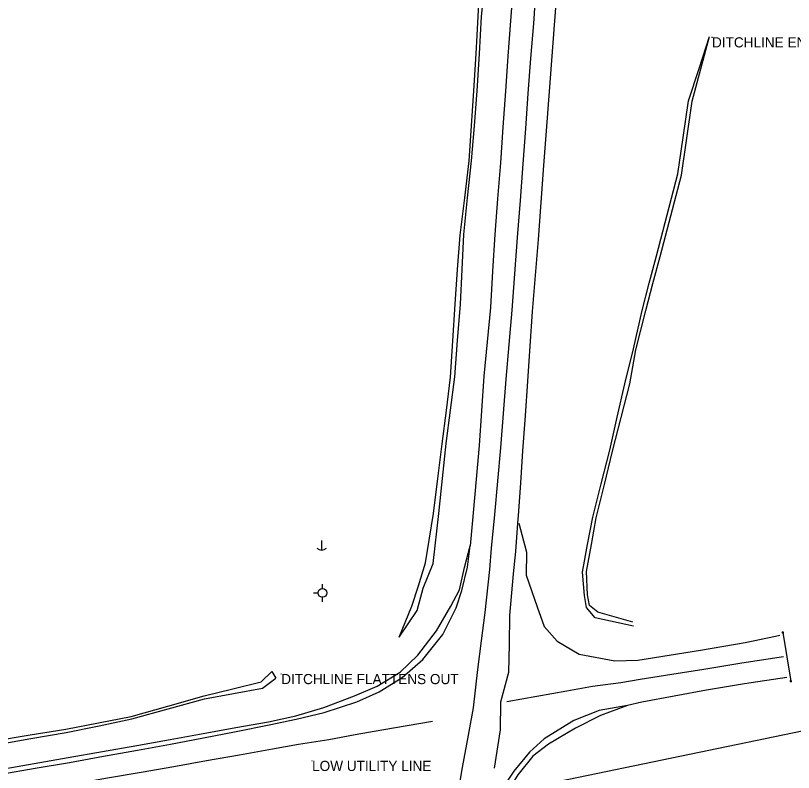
# Model space of a CAD drawing. Extents: x 1734049 to 1769984, y 344166 to 379510.
# Drawn here: x 1735978.3 to 1736361, y 378288.8 to 378661.3 of the extents above; entities that cross this region are included whole.
import ezdxf

# ---------------------------------------------------------------- set-up
doc = ezdxf.new("R2010")
doc.units = 0
for name, color, linetype in [('S_BASELINE', 7, 'Continuous'), ('S_BRIDGE', 7, 'Continuous'), ('S_DITCHLINE', 7, 'Continuous'), ('S_EDGE_PAVEMENT', 7, 'Continuous'), ('S_ELECTRIC_UTILITIES_ANNOT', 7, 'Continuous'), ('S_MSC_PT_SYM', 7, 'Continuous'), ('S_PAVEMENT_CROWN', 7, 'Continuous'), ('S_SHOULDER', 7, 'Continuous'), ('S_STR_PT_SYM', 7, 'Continuous'), ('S_SURVEY_TEXT_ANNOT', 7, 'Continuous'), ('S_UTILITY_POLE', 7, 'Continuous'), ('S_UTL_PT_SYM', 7, 'Continuous')]:
    doc.layers.add(name, color=color, linetype=linetype)

msp = doc.modelspace()

# ---------------------------------------------------------------- linework, layer by layer
at = {"layer": 'S_BASELINE'}
msp.add_line((1736142.34, 378263.18), (1737017.96, 378443.92), dxfattribs=at)
at = {"layer": 'S_BRIDGE'}
msp.add_line((1736355.87, 378357.66), (1736359.77, 378333.73), dxfattribs=at)
at = {"layer": 'S_DITCHLINE'}
for points in [[(1736166.97, 378355.41), (1736173.33, 378370.54), (1736176.51, 378380.59), (1736180, 378391.92), (1736183.91, 378416.22), (1736186.08, 378433.41), (1736188.26, 378450.6), (1736190.29, 378466.96), (1736192.32, 378483.33), (1736193.41, 378501.27), (1736194.51, 378519.21), (1736195.81, 378536.26), (1736197.11, 378553.32), (1736199.28, 378571.56), (1736201.45, 378589.8), (1736202.65, 378607.02), (1736203.84, 378624.23), (1736204.87, 378642.58), (1736205.89, 378660.93), (1736206.71, 378677.25)], [(1736166.97, 378355.41), (1736175.86, 378368.49), (1736178.79, 378379.51), (1736183.7, 378391.56), (1736186.47, 378416.28), (1736188.34, 378433.47), (1736190.21, 378450.66), (1736192.3, 378467.05), (1736194.4, 378483.44), (1736195.81, 378501.36), (1736197.22, 378519.27), (1736198.02, 378536.4), (1736198.82, 378553.54), (1736200.72, 378571.66), (1736202.61, 378589.78), (1736204.04, 378607.01), (1736205.48, 378624.24), (1736206.53, 378642.55), (1736207.58, 378660.87), (1736209.22, 378677.2)], [(1736282.39, 378360.8), (1736263.5, 378364.95), (1736259.24, 378369.92), (1736258.16, 378375.87), (1736257.22, 378387.43), (1736259.73, 378400.95), (1736262.25, 378414.47), (1736266.43, 378430.9), (1736270.61, 378447.33), (1736274.36, 378463.71), (1736278.1, 378480.1), (1736282.39, 378497.24), (1736286.63, 378516.13), (1736290.1, 378529.61), (1736293.58, 378543.08), (1736298.88, 378563.22), (1736304.18, 378583.35), (1736306.77, 378601.38), (1736309.36, 378619.41), (1736314.58, 378635.24), (1736319.79, 378651.08)], [(1736282.01, 378362.68), (1736264.78, 378367.72), (1736260.75, 378371.01), (1736259.7, 378376.15), (1736259.23, 378387.65), (1736261.63, 378400.9), (1736264.03, 378414.15), (1736268.05, 378430.5), (1736272.07, 378446.85), (1736276.29, 378463.46), (1736280.51, 378480.08), (1736283.43, 378496.82), (1736288.33, 378516.2), (1736291.9, 378529.43), (1736295.48, 378542.67), (1736300.71, 378562.74), (1736305.94, 378582.81), (1736308.56, 378601.01), (1736311.18, 378619.22), (1736315.49, 378635.15), (1736319.79, 378651.08)], [(1735967.77, 378304.3), (1735985.42, 378307.22), (1736003.06, 378310.15), (1736019.12, 378313.22), (1736035.18, 378316.28), (1736053.17, 378321.35), (1736071.17, 378326.42), (1736085.14, 378329.86), (1736099.11, 378333.29), (1736104.36, 378338.41), (1736106.32, 378335.19)], [(1735968.33, 378302.37), (1735985.79, 378305.41), (1736003.26, 378308.45), (1736019.39, 378311.78), (1736035.51, 378315.11), (1736053.35, 378320.04), (1736071.18, 378324.97), (1736085.52, 378327.65), (1736099.86, 378330.32), (1736106.32, 378335.19)]]:
    msp.add_lwpolyline(points, dxfattribs=at)
at = {"layer": 'S_EDGE_PAVEMENT'}
for points in [[(1736223.18, 378676.09), (1736221.77, 378658.68), (1736220.55, 378641.36), (1736219.33, 378624.05), (1736218.11, 378606.43), (1736216.89, 378588.81), (1736215.48, 378571.18), (1736214.06, 378553.54), (1736212.98, 378535.57), (1736211.9, 378517.6), (1736210.31, 378500.69), (1736208.72, 378483.77), (1736207.53, 378466.72), (1736206.34, 378449.66), (1736204.86, 378433.11), (1736203.38, 378416.55), (1736201.91, 378400.27)], [(1736244.61, 378674.03), (1736243.31, 378656.68), (1736241.97, 378639.23), (1736240.63, 378621.77), (1736239.36, 378604.61), (1736238.1, 378587.45), (1736236.75, 378569.31), (1736235.4, 378551.16), (1736233.92, 378533.43), (1736232.44, 378515.69), (1736231.31, 378498.55), (1736230.19, 378481.4), (1736228.95, 378464.26), (1736227.71, 378447.11), (1736226.68, 378431.18), (1736225.64, 378415.25), (1736225.3, 378411.48), (1736224.25, 378397.59), (1736223.1, 378386.54), (1736221.39, 378366.07), (1736221.14, 378351.99), (1736220.89, 378337.91), (1736216.9, 378323.29), (1736216.68, 378309.66), (1736213.82, 378290.92)], [(1736225.85, 378411.49), (1736229.7, 378397.16), (1736229.47, 378385.94), (1736235, 378370.32), (1736238.38, 378360.6), (1736244.76, 378353.39), (1736255.56, 378347.01), (1736273.2, 378343.77), (1736284.53, 378344), (1736299.94, 378346.5), (1736315.36, 378349), (1736337.21, 378352.73), (1736352.27, 378355.82), (1736354.28, 378356.3)], [(1735971.1, 378287.99), (1735987.96, 378290.84), (1736004.81, 378293.7), (1736021.55, 378296.71), (1736038.28, 378299.72), (1736054.51, 378302.72), (1736070.74, 378305.72), (1736086.88, 378308.93), (1736103.03, 378312.15), (1736116.36, 378315.03), (1736130.11, 378318.22), (1736146.15, 378323.6), (1736157.14, 378328.51), (1736168.46, 378335.5), (1736178.75, 378344.31), (1736188.46, 378356.63), (1736195.14, 378369.73), (1736197.94, 378378.3), (1736200.58, 378389.74), (1736201.91, 378400.27)], [(1736357.8, 378335.55), (1736337, 378332.4), (1736318.32, 378329.32), (1736302.4, 378326.31), (1736286.48, 378323.29), (1736279.34, 378321.72), (1736265.49, 378319.19), (1736252.94, 378314.26), (1736238.36, 378305.25), (1736231.18, 378298.74), (1736223.46, 378289.4), (1736215.41, 378277.17)]]:
    msp.add_lwpolyline(points, dxfattribs=at)
at = {"layer": 'S_MSC_PT_SYM'}
for points in [[(1736320.95, 378650.65), (1736320.95, 378650.7), (1736320.95, 378650.65), (1736320.9, 378650.65), (1736320.95, 378650.65), (1736320.95, 378650.6), (1736320.95, 378650.65), (1736321, 378650.65)], [(1736108.98, 378337.23), (1736108.98, 378337.28), (1736108.98, 378337.23), (1736108.93, 378337.23), (1736108.98, 378337.23), (1736108.98, 378337.18), (1736108.98, 378337.23), (1736109.03, 378337.23)]]:
    msp.add_lwpolyline(points, dxfattribs=at)
at = {"layer": 'S_PAVEMENT_CROWN'}
for points in [[(1736234.33, 378675.16), (1736233.05, 378657.41), (1736231.71, 378640.18), (1736230.37, 378622.95), (1736229.12, 378605.67), (1736227.88, 378588.39), (1736226.49, 378570.23), (1736225.1, 378552.07), (1736223.74, 378534.2), (1736222.39, 378516.34), (1736220.98, 378499.36), (1736219.56, 378482.39), (1736218.23, 378465.49), (1736216.9, 378448.6), (1736215.44, 378432.15), (1736213.98, 378415.71), (1736212.37, 378399.13), (1736211.51, 378388.69), (1736209.14, 378367.56), (1736207.35, 378353.51), (1736205.55, 378339.47), (1736203.48, 378320.64), (1736200.94, 378307.1), (1736198.07, 378291.2), (1736194.77, 378271.9)], [(1736356.13, 378345.68), (1736335.7, 378342.59), (1736316.93, 378339.45), (1736301.23, 378336.95), (1736285.53, 378334.45), (1736276.03, 378332.82), (1736262.14, 378330.99), (1736249.58, 378328.78), (1736234.83, 378326.18), (1736220.08, 378323.58)], [(1735972.71, 378277.41), (1735989.87, 378280.32), (1736007.03, 378283.22), (1736023.53, 378286.08), (1736040.04, 378288.94), (1736056.15, 378291.76), (1736072.26, 378294.57), (1736088.53, 378297.49), (1736104.79, 378300.41), (1736117.52, 378302.62), (1736132.36, 378305.06), (1736145.43, 378307.37), (1736158.51, 378309.67), (1736170.94, 378311.86), (1736183.36, 378314.05)]]:
    msp.add_lwpolyline(points, dxfattribs=at)
at = {"layer": 'S_SHOULDER'}
for points in [[(1735970.6, 378290.17), (1735987.41, 378293.19), (1736004.22, 378296.2), (1736021.12, 378299.1), (1736038.03, 378302), (1736054.31, 378304.96), (1736070.58, 378307.93), (1736086.69, 378310.82), (1736102.8, 378313.7), (1736116.22, 378316.63), (1736129.91, 378320.78), (1736145.06, 378326.42), (1736156.27, 378331.25), (1736167.52, 378338.16), (1736176.24, 378346.45), (1736185.45, 378358.44), (1736192.46, 378370.56), (1736196.78, 378378.67), (1736199.14, 378389.58), (1736201.91, 378400.27)], [(1736279.34, 378321.72), (1736266.15, 378316.86), (1736253.72, 378310.6), (1736240.47, 378302.68), (1736232.75, 378296.72), (1736225.36, 378287.59), (1736218.11, 378275.78), (1736210.03, 378256.3), (1736205.5, 378243.16), (1736200.97, 378230.03), (1736195.85, 378210.27), (1736194.14, 378189.63), (1736193.54, 378178.44), (1736194.83, 378155.51), (1736197.53, 378142.13), (1736200.23, 378128.76), (1736204.99, 378114.55), (1736209.74, 378100.34), (1736215.93, 378086.21), (1736222.13, 378072.08), (1736231.88, 378053.49), (1736240.27, 378038.26)]]:
    msp.add_lwpolyline(points, dxfattribs=at)
at = {"layer": 'S_STR_PT_SYM'}
for points in [[(1736355.87, 378357.66), (1736355.87, 378358.16), (1736355.87, 378357.66), (1736355.37, 378357.66), (1736355.87, 378357.66), (1736355.87, 378357.16), (1736355.87, 378357.66), (1736356.37, 378357.66)], [(1736359.77, 378333.73), (1736359.77, 378334.23), (1736359.77, 378333.73), (1736359.27, 378333.73), (1736359.77, 378333.73), (1736359.77, 378333.23), (1736359.77, 378333.73), (1736360.27, 378333.73)]]:
    msp.add_lwpolyline(points, dxfattribs=at)
at = {"layer": 'S_UTILITY_POLE'}
for p, q in [((1736128.8, 378402.93), (1736128.8, 378398.2)), ((1736129.24, 378379.22), (1736129.24, 378381.46)), ((1736127.14, 378377.08), (1736124.82, 378377.08)), ((1736129.31, 378372.67), (1736129.31, 378374.99))]:
    msp.add_line(p, q, dxfattribs=at)
msp.add_circle((1736129.24, 378377.11), 2.13, dxfattribs=at)
msp.add_arc((1736128.86, 378401.62), 3.41, 226.3972, 313.6028, dxfattribs=at)
at = {"layer": 'S_UTL_PT_SYM'}
msp.add_lwpolyline([(1736124.19, 378294.49), (1736124.19, 378294.54), (1736124.19, 378294.49), (1736124.14, 378294.49), (1736124.19, 378294.49), (1736124.19, 378294.44), (1736124.19, 378294.49), (1736124.24, 378294.49)], dxfattribs=at)

# ---------------------------------------------------------------- texts
at = {"layer": 'S_ELECTRIC_UTILITIES_ANNOT'}
msp.add_text('LOW UTILITY LINE', height=5, dxfattribs=at).set_placement((1736124.19, 378289.49))
at = {"layer": 'S_SURVEY_TEXT_ANNOT'}
for s, p in [('DITCHLINE ENDS', (1736320.95, 378645.65)), ('DITCHLINE FLATTENS OUT', (1736108.98, 378332.23))]:
    msp.add_text(s, height=5, dxfattribs=at).set_placement(p)

doc.saveas('drawing.dxf')
